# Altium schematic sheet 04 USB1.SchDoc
size 420 x 297 mm; DocumentNumber: 4; SheetNumber: 4; SheetTotal: 12
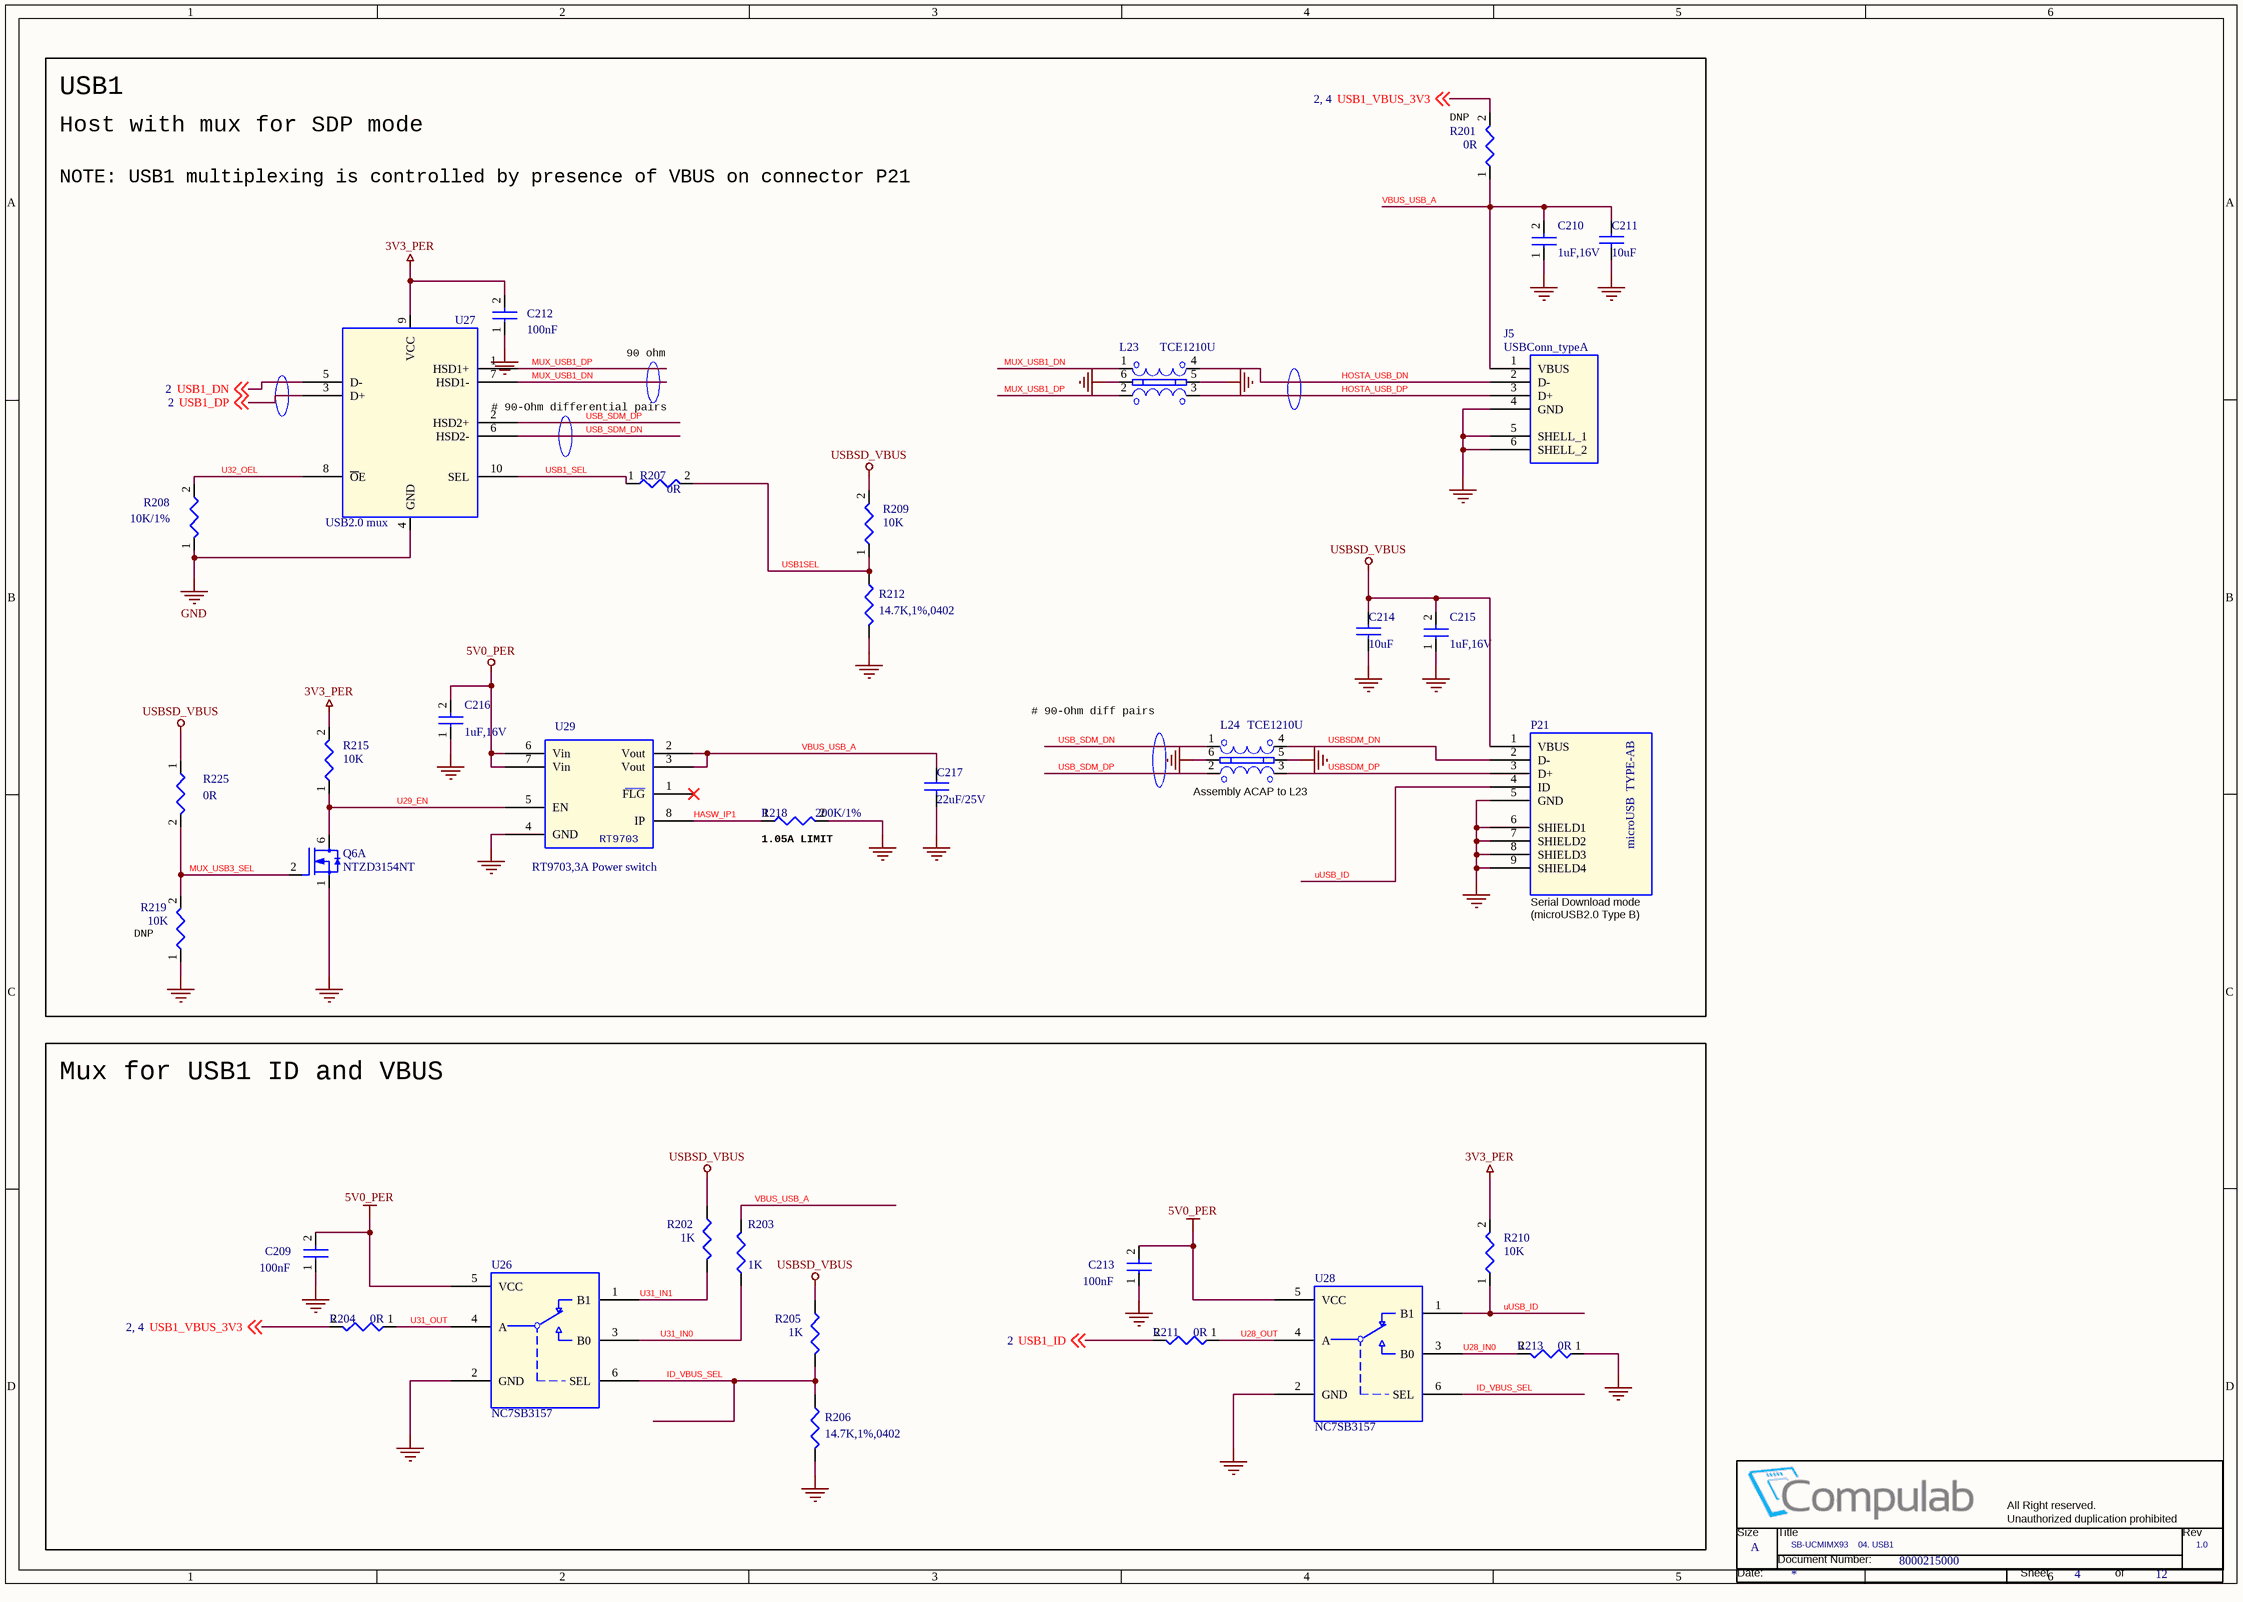
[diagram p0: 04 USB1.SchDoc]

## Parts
*  Title: SB-UCMIMX93    04. USB1  Doc: 8000215000  RevCode: 1.0  Page Size: A  Page Number: 4  Page Count: 12  (hidden comment: CompuLabTitleBlk)  (graphical)
C209  100nF  [RC0402]
C210  1uF,16V  [RC0402]
C211  10uF  [C0603-08]
C212  100nF  [RC0402]
C213  100nF  [RC0402]
C214  10uF  [C0603-08]
C215  1uF,16V  [RC0402]
C216  1uF,16V  [RC0402]
C217  22uF/25V  [C0805]
J5  USBConn_typeA  [USB-A-SM]
L23  TCE1210U  [EMI1012-ESD]
L24  TCE1210U  [EMI1012-ESD]
P21  microUSB  TYPE-AB  [MICRO-USB-AB-RA-SM]
Q6  NTZD3154NT  [SOT-563-6]  (part A of 2)
R201  0R  [RC0402]
R202  1K  [RC0402]
R203  1K  [RC0402]
R204  0R  [RC0402]
R205  1K  [RC0402]
R206  14.7K,1%,0402  [RC0402]
R207  0R  [RC0402]
R208  10K/1%  [RC0402]
R209  10K  [RC0402]
R210  10K  [RC0402]
R211  0R  [RC0402]
R212  14.7K,1%,0402  [RC0402]
R213  0R  [RC0402]
R215  10K  [RC0402]
R218  200K/1%  [RC0402]
R219  10K  [RC0402]
R225  0R  [RC0402]
U26  NC7SB3157  [SC70-6]
U27  USB2.0 mux  [MO-255U1418E]
U28  NC7SB3157  [SC70-6]
U29  RT9703,3A Power switch  [SO8-150]

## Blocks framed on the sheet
USB1: C210-C212 C214-C217 J5 L23 L24 P21 Q6 R201 R207-R209 R212 R215 R218 R219 R225 U27 U29
Mux for USB1 ID and VBUS: C209 C213 R202-R206 R210 R211 R213 U26 U28

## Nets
3V3_PER: C212.2 R210.2 R215.2 U27.9(VCC)
5V0_PER: C209.2 C213.2 C216.2 U26.5(VCC) U28.5(VCC) U29.6(Vin) U29.7(Vin)
GND: C209.1 C210.1 C211.2 C212.1 C213.1 C214.2 C215.1 C216.1 C217.2 J5.4(GND) J5.5(SHELL_1) J5.6(SHELL_2) L23.5(GND) L23.6(GND) L24.5(GND) L24.6(GND) P21.5(GND) P21.6(SHIELD1) P21.7(SHIELD2) P21.8(SHIELD3) P21.9(SHIELD4) Q6.1(S) R206.2 R208.1 R212.2 R213.1 R218.2 R219.1 U26.2(GND) U27.4(GND) U28.2(GND) U29.4(GND)
USBSD_VBUS: C214.1 C215.2 P21.1(VBUS) R202.1 R205.1 R209.2 R225.1
HASW_IP1: R218.1 U29.8(IP)
HOSTA_USB_DN: J5.2(D-) L23.4
HOSTA_USB_DP: J5.3(D+) L23.3
ID_VBUS_SEL: R205.2 R206.1 U26.6(SEL) U28.6(SEL)
MUX_USB1_DN: L23.1 U27.7(HSD1-)
MUX_USB1_DP: L23.2 U27.1(HSD1+)
MUX_USB3_SEL: Q6.2(G) R219.2 R225.2
U28_IN0: R213.2 U28.3(B0)
U28_OUT: R211.1 U28.4(A)
U29_EN: Q6.6(D) R215.1 U29.5(EN)
U31_IN0: R203.2 U26.3(B0)
U31_IN1: R202.2 U26.1(B1)
U31_OUT: R204.1 U26.4(A)
U32_OEL: R208.2 U27.8(~{O}E)
USB1_DN: U27.5(D-) ; off-sheet USB1_DN
USB1_DP: U27.3(D+) ; off-sheet USB1_DP
USB1_ID: R211.2 ; off-sheet USB1_ID
USB1_SEL: R207.1 U27.10(SEL)
USB1_VBUS_3V3: R201.2 R204.2 ; off-sheet USB1_VBUS_3V3
USB1SEL: R207.2 R209.1 R212.1
USB_SDM_DN: L24.1 U27.6(HSD2-)
USB_SDM_DP: L24.2 U27.2(HSD2+)
USBSDM_DN: L24.4 P21.2(D-)
USBSDM_DP: L24.3 P21.3(D+)
uUSB_ID: P21.4(ID) R210.1 U28.1(B1)
VBUS_USB_A: C210.2 C211.1 C217.1 J5.1(VBUS) R201.1 R203.1 U29.2(Vout) U29.3(Vout)

Not connected (* = marked no-connect by the designer): U29 1(FLG)*

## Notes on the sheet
- (near R201) DNP
- Host with mux for SDP mode
- NOTE: USB1 multiplexing is controlled by presence of VBUS on connector P21
- 90 ohm
- (near U27) # 90-Ohm differential pairs
- # 90-Ohm diff pairs
- (near L24) Assembly ACAP to L23
- (near R218) 1.05A LIMIT
- (near R219) DNP
- (near P21) Serial Download mode
  (microUSB2.0 Type B)

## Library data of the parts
C209 C212 C213 = 100nF, 10V, X7R, 10%, 0402_Dup1: P/N: 151B10400S; Group: LAN2
C210 C215 C216 = 100nF, 10V, X7R, 10%, 0402: P/N: 151C10500S
C211 C214 = 10uF,6_0.3V,0603,20%X5R: P/N: 151B10610S
C217 = 22uF,25V, 0805: P/N: 151C22620S
J5 = USB Conn., Fem, Type A , TH, RA: P/N: 180K00400S
L23 L24 = ESD_CHOKE_DIFFx2_10: P/N: 142D11801S
P21 = Conn., Micro-USB, B-Type: P/N: 180K00501S
Q6 = N-MOSFET_Dual: P/N: 131D31540S
R201 = 0R, 0402: P/N: 161C00005S; CLABCONF0: DNP
R202 R203 R205 = RESISTOR_Dup1: P/N: 161C10011S
R204 R207 R211 R213 R225 = 0R, 0402: P/N: 161C00005S
R206 R212 = RESISTOR_Dup1: P/N: 161C14721S
R208 = 10K,1%,0402,1/16W_0_Dup1: P/N: 161C10021S
R209 R210 R215 = 1M ,5%, 0402: P/N: 161C10021S
R218 = 100K, 1%, 0402, 1/16W: P/N: 161C20031S
R219 = 1M ,5%, 0402: P/N: 161C10021S; CLABCONF0: DNP
U26 U28 = Bus switch 2:1: P/N: 124S10050S
U27 = USB2_0.0 mux: P/N: 116A72220S
U29 = RT9703,3A Power switch+FLG: P/N: 124S10080S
